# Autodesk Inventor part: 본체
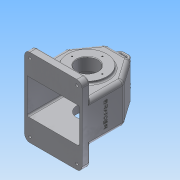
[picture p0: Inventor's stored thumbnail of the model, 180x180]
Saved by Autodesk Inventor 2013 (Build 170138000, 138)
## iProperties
Created: 2016-12
Part Number: 본체
Material: 알루미늄 6061
Document SubType Name: Modeling
Designer: Administrator
Density: 2.71 g/cm^3
Mass: 1066.6 g
Surface Area: 1139.62 cm^2
Volume: 393.578 cm^3
Author: Administrator
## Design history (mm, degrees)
sketch "스케치1"
  geometry: L1 (-55, -65)-(55, -65); L2 (55, -65)-(55, 15); L3 (55, 15)-(23.491, 60); L4 (23.491, 60)-(-23.491, 60); L5 (-23.491, 60)-(-55, 15); L6 (-55, 15)-(-55, -65); 2 further points
  constraints: 12 end point, 2 perpendicular, 1 equal length, 1 horizontal, 1 midpoint, 1 parallel, 1 vertical alignment
  dimensions: "d1" = 65 distance from line of L1 point (0, 0); "d2" = 80 distance of L1.end L2.end; "d3" = 35 deg angle of L2 L3; "d4" = 35 deg angle of L6 L5; "d5" = 125 distance between parallel lines of L1 L4; "d6" = 110 distance of L1.start L1.end
extrude "돌출1" new body sketch "스케치1" stored distance "d7" = 77; taper "d8" = 0 deg
feature "쉘1" dims "d9" = 5
sketch "스케치3"
  geometry: C1 r 37.5 at (0, 0); 1 further point
  constraints: 1 centre point, 1 coincident
  dimensions: "d10" = 75 diameter of C1
extrude "돌출2" join sketch "스케치3" distance "d12" = 5; taper "d13" = 0 deg
sketch "스케치4"
  geometry: C1 r 31 at (0, 0); 1 further point
  constraints: 1 centre point, 1 coincident
  dimensions: "d14" = 62 diameter of C1
extrude "돌출3" join sketch "스케치4" distance "d16" = 10; taper "d17" = 0 deg
sketch "스케치5"
  geometry: L1 (55, 33.5)-(13.424, 33.5) reference; L2 (13.424, 33.5)-(-65, 33.5) reference; L3 (41, 33.5)-(27, 19.5); L4 (27, 19.5)-(0, 19.5); L5 (0, 19.5)-(0, 33.5); L6 (37.5, 43.5)-(-37.5, 43.5) reference; 2 further points
  constraints: 6 end point, 2 point on line, 1 midpoint, 1 parallel, 1 perpendicular, 1 vertical alignment
  dimensions: "d18" = 45 deg angle of L4 L3; "d19" = 27 distance of L3.end L4.end; "d22" = 24 distance between parallel lines of L4 L6
revolve "회전1" sketch "스케치5" stored, may be unused: angle "d23" = 90 deg
sketch "스케치6"
  geometry: L1 (110, -77)-(110, 0) reference; L2 (0, 0)-(110, 0) reference; L3 (0, 0)-(0, -77) reference; L4 (110, -77)-(0, -77) reference; L5 (0, -113.5)-(110, -113.5); L6 (110, -113.5)-(110, 36.5); L7 (110, 36.5)-(0, 36.5); L8 (0, 36.5)-(0, -113.5); L9 (0, -113.5)-(110, 36.5); L10 (110, -113.5)-(0, 36.5); 1 further point
  constraints: 12 end point, 2 midpoint, 2 parallel, 1 horizontal, 1 perpendicular
  dimensions: "d24" = 110 distance of L6.end L7.end; "d26" = 150 distance of L7.end L5.start
extrude "돌출4" join sketch "스케치6" distance "d27" = 15; taper "d28" = 0 deg
sketch "스케치7"
  geometry: C1 r 37.5 at (0, 0) reference; C2 r 20 at (0, 0)
  constraints: 1 centre point, 1 coincident
  dimensions: "d29" = 40 diameter of C2
extrude "돌출5" cut sketch "스케치7" stored distance "d31" = 15; taper "d32" = 0 deg
sketch "스케치8"
  geometry: L1 (10.991, 20.5)-(35.991, 20.5); L2 (35.991, 20.5)-(35.991, 12.5); L3 (35.991, 12.5)-(10.991, 12.5); L4 (10.991, 12.5)-(10.991, 20.5); 2 further points
  constraints: 8 end point, 2 parallel, 1 horizontal, 1 midpoint, 1 perpendicular, 1 vertical alignment
  dimensions: "d33" = 12.5 distance from line of point (23.491, 38.5) L2; "d35" = 8 distance of L1.end L2.end; "d36" = 18 distance from line of point (23.491, 38.5) L1
extrude "돌출6" join sketch "스케치8" distance "d37" = 15; taper "d38" = 0 deg
fillet "모깎기1" dims "d39" = 8
sketch "스케치9"
  geometry: L1 (25, 0)-(0, 0) reference; L2 (25, 0)-(25, 7) reference; L3 (8, 15)-(17, 15) reference; L4 (20, 7)-(20, 0); L5 (5, 0)-(5, 7); L6 (8, 10)-(17, 10); A1 r 8 centre (8, 7) between (8, 15) and (0, 7) reference; A2 r 8 centre (17, 7) between (25, 7) and (17, 15) reference; A3 r 3 centre (17, 7) between (20, 7) and (17, 10); A4 r 3 centre (8, 7) between (8, 10) and (5, 7); 1 further point
  constraints: 6 end point, 4 point on circle, 2 centre point, 2 point on line, 1 equal radius, 1 parallel, 1 tangent, 1 other
  dimensions: "d40" = 5 distance between parallel lines of L3 L6; "d41" = 5 distance between parallel lines of L2 L4
extrude "돌출7" cut sketch "스케치9" distance "d42" = 15; taper "d43" = 0 deg
fillet "모깎기3" dims "d45" = 1
fillet "모깎기4" dims "d46" = 10
hole "구멍1" diameter "d49" = 5; stored, may be unused: countersink angle "d53" = 90 deg, drill point angle "d55" = 118 deg; dims "d47" = 10, "d48" = 10, "d50" = 6, "d51" = 12, "d52" = 5, "d54" = 8
hole "구멍2" diameter "d58" = 5; stored, may be unused: countersink angle "d62" = 90 deg, drill point angle "d64" = 118 deg; dims "d56" = 10, "d57" = 10, "d59" = 6, "d60" = 12, "d61" = 5, "d63" = 8
hole "구멍3" diameter "d67" = 5; stored, may be unused: countersink angle "d71" = 90 deg, drill point angle "d73" = 118 deg; dims "d65" = 10, "d66" = 10, "d68" = 6, "d69" = 12, "d70" = 5, "d72" = 8
hole "구멍4" diameter "d76" = 5; stored, may be unused: countersink angle "d80" = 90 deg, drill point angle "d82" = 118 deg; dims "d74" = 10, "d75" = 10, "d77" = 6, "d78" = 12, "d79" = 5, "d81" = 8
fillet "모깎기5" dims "d83" = 10
fillet "모깎기6" dims "d84" = 8, "d85" = 3
fillet "모깎기7" dims "d86" = 3
fillet "모깎기8" dims "d87" = 3
sketch "스케치11"
  geometry: C1 r 20 at (0, 0) reference; 1 further point
  constraints: 1 vertical alignment
  dimensions: "d88" = 29 distance of C1.centre point (0, 29)
hole "구멍5" sketch "스케치11" at (0, 29) diameter "d89" = 2.459; stored, may be unused: countersink angle "d93" = 90 deg, drill point angle "d95" = 118 deg; dims "d90" = 6, "d91" = 12, "d92" = 5, "d94" = 8
sketch "스케치12"
  geometry: C1 r 20 at (0, 0) reference; 1 further point
  constraints: 1 vertical alignment
  dimensions: "d99" = 26 distance of C1.centre point (0, 26)
hole "구멍6" sketch "스케치12" at (0, 26) diameter "d100" = 2.459; stored, may be unused: countersink angle "d104" = 90 deg, drill point angle "d106" = 118 deg; dims "d101" = 6, "d102" = 12, "d103" = 5, "d105" = 8
chamfer "모따기1" distance "d110" = 1; stored, may be unused: second distance "d111" = 2, angle "d112" = 45 deg
fillet "모깎기9" dims "d113" = 3
sketch "스케치13" dims "d1" = 65, "d2" = 80, "d3" = 35 deg, "d4" = 35 deg, "d5" = 125, "d6" = 110
  geometry: L1 (130, 0)-(0, 0) reference; L2 (26.5, 76.847)-(26.5, 18) reference; 2 further points
  constraints: 1 other
  dimensions: "d114" = 38.5 distance from line of point (65, 45) L2; "d115" = 45 distance from line of L1 point (65, 45)
feature "엠보싱1" sketch "스케치13" dims "d16" = 10, "d17" = 0, "d116" = 0.5, "d117" = 0
fillet "모깎기10" dims "d118" = 1
node "솔리드1"
mirror "대칭2"
pattern_circular "원형 패턴1" dims angle "d97" = 360 deg
pattern_circular "원형 패턴2" dims angle "d108" = 360 deg
